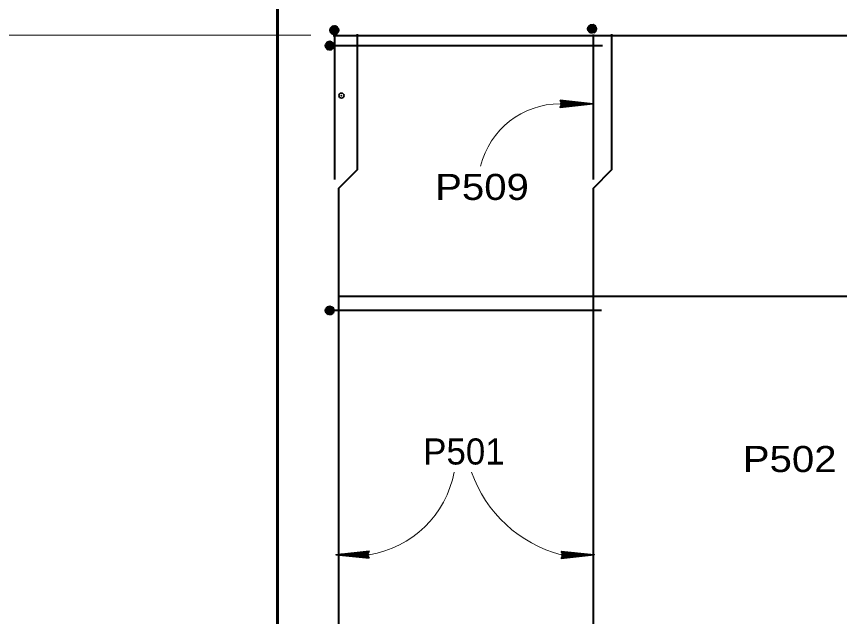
# Model space of a CAD drawing. Extents: x 4.49 to 7.69, y 0.28 to 2.27.
# Drawn here: x 4.7957 to 5.0586, y 0.8124 to 1.004 of the extents above; entities that cross this region are included whole.
import ezdxf

# ---------------------------------------------------------------- set-up
doc = ezdxf.new("R2010")
doc.units = 0
doc.header["$LTSCALE"] = 0.0033
doc.header["$PDMODE"] = 32
doc.header["$PDSIZE"] = 0.00165
doc.layers.add('1', color=7, linetype='Continuous', lineweight=35)

msp = doc.modelspace()

# ---------------------------------------------------------------- linework, layer by layer
at = {"layer": '1', "lineweight": 40}
for p, q in [((4.89625, 0.998833), (4.896583, 1.00075)), ((4.896417, 0.99875), (4.89675, 1.00075)), ((4.896417, 0.99975), (4.897917, 0.999667)), ((4.896417, 0.999667), (4.897917, 0.999583)), ((4.896417, 0.999583), (4.897917, 0.9995)), ((4.896417, 0.9995), (4.897917, 0.999417)), ((4.896417, 0.999417), (4.897917, 0.999333)), ((4.896417, 0.999333), (4.897917, 0.99925)), ((4.896417, 0.99925), (4.897917, 0.999167)), ((4.896417, 0.999083), (4.897917, 0.999)), ((4.896417, 0.999), (4.897917, 0.998917)), ((4.896417, 0.998917), (4.897917, 0.998833)), ((4.8965, 1.000833), (4.898, 1.00075)), ((4.8965, 0.99875), (4.896833, 1.00075)), ((4.8965, 1.000667), (4.898, 1.000583)), ((4.8965, 1.000583), (4.898, 1.0005)), ((4.8965, 1.0005), (4.898, 1.000417)), ((4.8965, 1.000417), (4.898, 1.000333)), ((4.8965, 1.000333), (4.898, 1.00025)), ((4.8965, 1.00025), (4.898, 1.000167)), ((4.8965, 1.000167), (4.898, 1.000083)), ((4.8965, 1.000167), (4.898, 1.000083)), ((4.8965, 1.000083), (4.898, 0.999917)), ((4.8965, 0.999917), (4.898, 0.99975)), ((4.896583, 0.99875), (4.897, 1.00075)), ((4.896667, 0.99875), (4.897083, 1.00075)), ((4.896833, 0.99875), (4.897167, 1.000667)), ((4.896917, 0.998667), (4.89725, 1.000667)), ((4.897, 0.998667), (4.897417, 1.000667)), ((4.897083, 0.998667), (4.8975, 1.000583)), ((4.897167, 0.998667), (4.897583, 1.000583)), ((4.897333, 0.998583), (4.89775, 1.000583)), ((4.897583, 0.998583), (4.897917, 1.000583)), ((4.897667, 0.998583), (4.898, 1.0005)), ((4.89775, 0.998583), (4.898083, 1.0005)), ((4.897833, 0.9985), (4.898167, 1.0005)), ((4.978583, 0.99925), (4.978917, 1.001167)), ((4.97875, 0.999167), (4.979083, 1.001167)), ((4.97875, 1.000167), (4.98025, 1.000083)), ((4.97875, 1.000083), (4.98025, 1)), ((4.97875, 1), (4.98025, 0.999917)), ((4.97875, 0.999917), (4.98025, 0.999833)), ((4.97875, 0.999833), (4.98025, 0.99975)), ((4.97875, 0.99975), (4.98025, 0.999667)), ((4.97875, 0.999667), (4.98025, 0.999583)), ((4.97875, 0.9995), (4.98025, 0.999417)), ((4.97875, 0.999417), (4.98025, 0.999333)), ((4.97875, 0.999333), (4.98025, 0.99925)), ((4.97875, 0.99925), (4.98025, 0.999167)), ((4.97875, 0.999167), (4.98025, 0.999083)), ((4.978833, 1.00125), (4.980333, 1.001167)), ((4.978833, 0.999167), (4.979167, 1.001167)), ((4.978833, 1.001083), (4.980333, 1.001)), ((4.978833, 1.001), (4.980333, 1.000917)), ((4.978833, 1.000917), (4.980333, 1.000833)), ((4.978833, 1.000833), (4.980333, 1.00075)), ((4.978833, 1.00075), (4.980333, 1.000667)), ((4.978833, 1.000667), (4.980333, 1.000583)), ((4.978833, 1.000583), (4.980333, 1.0005)), ((4.978833, 1.000583), (4.980333, 1.0005)), ((4.978833, 1.0005), (4.980333, 1.000333)), ((4.978833, 1.000333), (4.980333, 1.000167)), ((4.978917, 0.999167), (4.979333, 1.001167)), ((4.979, 0.999167), (4.979417, 1.001167)), ((4.979167, 0.999167), (4.9795, 1.001083)), ((4.97925, 0.999083), (4.979583, 1.001083)), ((4.979333, 0.999083), (4.97975, 1.001083)), ((4.979417, 0.999083), (4.979833, 1.001)), ((4.9795, 0.999083), (4.979917, 1.001)), ((4.979667, 0.999), (4.980083, 1.001)), ((4.979917, 0.999), (4.98025, 1.001)), ((4.98, 0.999), (4.980333, 1.000917)), ((4.980083, 0.999), (4.980417, 1.000917)), ((4.980167, 0.998917), (4.9805, 1.000917)), ((4.896417, 0.998833), (4.897917, 0.99875)), ((4.896417, 0.99875), (4.897917, 0.998667)), ((4.89725, 0.99825), (4.89725, 0.951917)), ((4.979833, 0.99825), (4.979833, 0.951917)), ((4.894583, 0.994), (4.894667, 0.9955)), ((4.896667, 0.994167), (4.894667, 0.994583)), ((4.896667, 0.994083), (4.894667, 0.9945)), ((4.896667, 0.994), (4.894667, 0.994333)), ((4.896667, 0.993917), (4.894667, 0.99425)), ((4.896583, 0.99375), (4.894667, 0.994083)), ((4.89475, 0.994), (4.894833, 0.9955)), ((4.89675, 0.9945), (4.89475, 0.994917)), ((4.89675, 0.994417), (4.89475, 0.99475)), ((4.896667, 0.994333), (4.89475, 0.994667)), ((4.894833, 0.994), (4.894917, 0.9955)), ((4.896833, 0.995083), (4.894833, 0.995417)), ((4.896833, 0.994833), (4.894833, 0.99525)), ((4.89675, 0.994667), (4.894833, 0.995083)), ((4.89675, 0.994583), (4.894833, 0.995)), ((4.896917, 0.995333), (4.894917, 0.995667)), ((4.896833, 0.99525), (4.894917, 0.995583)), ((4.894917, 0.994), (4.895, 0.9955)), ((4.896833, 0.995167), (4.894917, 0.9955)), ((4.895, 0.994), (4.895083, 0.9955)), ((4.895083, 0.994), (4.895167, 0.9955)), ((4.895167, 0.994), (4.89525, 0.9955)), ((4.89525, 0.994), (4.895333, 0.9955)), ((4.89525, 0.994), (4.895333, 0.9955)), ((4.895333, 0.994), (4.8955, 0.9955)), ((4.8955, 0.994), (4.895667, 0.9955)), ((4.895667, 0.993917), (4.89575, 0.995417)), ((4.89575, 0.993917), (4.895833, 0.995417)), ((4.895833, 0.993917), (4.895917, 0.995417)), ((4.895917, 0.993917), (4.896, 0.995417)), ((4.896, 0.993917), (4.896083, 0.995417)), ((4.896083, 0.993917), (4.896167, 0.995417)), ((4.896167, 0.993917), (4.89625, 0.995417)), ((4.896333, 0.993917), (4.896417, 0.995417)), ((4.896417, 0.993917), (4.8965, 0.995417)), ((4.8965, 0.993917), (4.896583, 0.995417)), ((4.896583, 0.993917), (4.896667, 0.995417)), ((4.896667, 0.993917), (4.89675, 0.995417)), ((4.897167, 0.99475), (4.982833, 0.99475)), ((4.8985, 0.914667), (5.122167, 0.914667)), ((4.894583, 0.909417), (4.894667, 0.910917)), ((4.896667, 0.909583), (4.894667, 0.91)), ((4.896667, 0.9095), (4.894667, 0.909917)), ((4.896667, 0.909417), (4.894667, 0.90975)), ((4.896667, 0.909333), (4.894667, 0.909667)), ((4.896583, 0.909167), (4.894667, 0.9095)), ((4.89475, 0.909417), (4.894833, 0.910917)), ((4.89675, 0.909917), (4.89475, 0.910333)), ((4.89675, 0.909833), (4.89475, 0.910167)), ((4.896667, 0.90975), (4.89475, 0.910083)), ((4.894833, 0.909417), (4.894917, 0.910917)), ((4.896833, 0.9105), (4.894833, 0.910833)), ((4.896833, 0.91025), (4.894833, 0.910667)), ((4.89675, 0.910083), (4.894833, 0.9105)), ((4.89675, 0.91), (4.894833, 0.910417)), ((4.896917, 0.91075), (4.894917, 0.911083)), ((4.896833, 0.910667), (4.894917, 0.911)), ((4.894917, 0.909417), (4.895, 0.910917)), ((4.896833, 0.910583), (4.894917, 0.910917)), ((4.895, 0.909417), (4.895083, 0.910917)), ((4.895083, 0.909417), (4.895167, 0.910917)), ((4.895167, 0.909417), (4.89525, 0.910917)), ((4.89525, 0.909417), (4.895333, 0.910917)), ((4.89525, 0.909417), (4.895333, 0.910917)), ((4.895333, 0.909417), (4.8955, 0.910917)), ((4.8955, 0.909417), (4.895667, 0.910917)), ((4.895667, 0.909333), (4.89575, 0.910833)), ((4.89575, 0.909333), (4.895833, 0.910833)), ((4.895833, 0.909333), (4.895917, 0.910833)), ((4.895917, 0.909333), (4.896, 0.910833)), ((4.896, 0.909333), (4.896083, 0.910833)), ((4.896083, 0.909333), (4.896167, 0.910833)), ((4.896167, 0.909333), (4.89625, 0.910833)), ((4.896333, 0.909333), (4.896417, 0.910833)), ((4.896417, 0.909333), (4.8965, 0.910833)), ((4.8965, 0.909333), (4.896583, 0.910833)), ((4.896583, 0.909333), (4.896667, 0.910833)), ((4.896667, 0.909333), (4.89675, 0.910833)), ((4.897167, 0.910167), (4.9825, 0.910167))]:
    msp.add_line(p, q, dxfattribs=at)
at = {"layer": '1', "lineweight": 13}
msp.add_line((4.88975, 0.998083), (4.7125, 0.998083), dxfattribs=at)
at = {"layer": '1'}
for p, q in [((4.969333, 0.976167), (4.979917, 0.976167)), ((4.9695, 0.9755), (4.976833, 0.97625)), ((4.969583, 0.977167), (4.977417, 0.97625)), ((4.969583, 0.977167), (4.977417, 0.97625)), ((4.969583, 0.977083), (4.977417, 0.97625)), ((4.969583, 0.977), (4.977417, 0.976167)), ((4.969583, 0.977), (4.977417, 0.976)), ((4.969583, 0.975333), (4.976917, 0.976167)), ((4.969583, 0.97525), (4.976917, 0.976)), ((4.969583, 0.975083), (4.976917, 0.975917)), ((4.908333, 0.832083), (4.89775, 0.832083)), ((4.908083, 0.83125), (4.90025, 0.83225)), ((4.908083, 0.83125), (4.90025, 0.832083)), ((4.908083, 0.831083), (4.90025, 0.832)), ((4.908083, 0.831083), (4.90025, 0.832)), ((4.908083, 0.831167), (4.90025, 0.832)), ((4.908083, 0.833167), (4.90075, 0.832333)), ((4.908083, 0.833), (4.90075, 0.83225)), ((4.908083, 0.832917), (4.90075, 0.832083)), ((4.908167, 0.83275), (4.900833, 0.832)), ((4.969667, 0.832083), (4.98025, 0.832083)), ((4.969833, 0.831417), (4.977167, 0.832167)), ((4.969917, 0.833083), (4.97775, 0.832167)), ((4.969917, 0.833083), (4.97775, 0.832167)), ((4.969917, 0.833), (4.97775, 0.832167)), ((4.969917, 0.832917), (4.97775, 0.832083)), ((4.969917, 0.832917), (4.97775, 0.831917)), ((4.969917, 0.83125), (4.97725, 0.832083)), ((4.969917, 0.831167), (4.97725, 0.831917)), ((4.969917, 0.831), (4.97725, 0.831833))]:
    msp.add_line(p, q, dxfattribs=at)
at = {"layer": '1', "lineweight": 60}
msp.add_lwpolyline([(4.79575, 0.599083), (4.79575, 0.682417), (4.879083, 0.682417), (4.879083, 1.01575)], dxfattribs=at)
at = {"layer": '1', "lineweight": 40}
for points in [[(4.89725, 0.998333), (4.896917, 1.000917), (4.896417, 0.998583), (4.8975, 1.000917), (4.897917, 0.9985), (4.89825, 1.0005), (4.896167, 1.0005), (4.8985, 0.999583), (4.895917, 0.999833), (4.89825, 0.998833), (4.895917, 0.999167), (4.8985, 1), (4.89675, 0.998417), (4.896583, 1.000833), (4.898417, 0.999167), (4.896, 1.00025), (4.896417, 0.998583), (4.897917, 0.9985), (4.8985, 0.999583), (4.89825, 1.0005), (4.8975, 1.000917), (4.896583, 1.000833), (4.896, 1.00025), (4.897083, 0.999583), (4.898, 1.00075), (4.89825, 0.998833), (4.897083, 0.999583), (4.896583, 0.9985), (4.895917, 0.9995), (4.897, 0.999583), (4.89825, 1.000417), (4.897, 0.998417), (4.896667, 0.99975), (4.896167, 1.0005)], [(4.979583, 0.99875), (4.97925, 1.001333), (4.97875, 0.999), (4.979833, 1.001333), (4.98025, 0.998917), (4.980583, 1.000917), (4.9785, 1.000917), (4.980833, 1), (4.97825, 1.00025), (4.980583, 0.99925), (4.97825, 0.999583), (4.980833, 1.000417), (4.979083, 0.998833), (4.978917, 1.00125), (4.98075, 0.999583), (4.978333, 1.000667), (4.97875, 0.999), (4.98025, 0.998917), (4.980833, 1), (4.980583, 1.000917), (4.979833, 1.001333), (4.978917, 1.00125), (4.978333, 1.000667), (4.979417, 1), (4.980333, 1.001167), (4.980583, 0.99925), (4.979417, 1), (4.978917, 0.998917), (4.97825, 0.999917), (4.979333, 1), (4.980583, 1.000833), (4.979333, 0.998833), (4.979, 1.000167), (4.9785, 1.000917)], [(4.896833, 0.998), (5.122333, 0.998), (5.4505, 0.998)], [(4.9045, 0.998333), (4.9045, 0.955), (4.898583, 0.949083), (4.898583, 0.74075), (4.9045, 0.734833), (4.9045, 0.688583)], [(4.98575, 0.998333), (4.98575, 0.955), (4.979833, 0.949083), (4.979833, 0.74075), (4.98575, 0.734833), (4.98575, 0.688583)], [(4.897083, 0.99475), (4.8945, 0.994417), (4.896833, 0.993917), (4.8945, 0.995), (4.896917, 0.995417), (4.894917, 0.99575), (4.894917, 0.993667), (4.895833, 0.996), (4.895583, 0.993417), (4.896583, 0.99575), (4.89625, 0.993417), (4.895417, 0.996), (4.897, 0.99425), (4.894583, 0.994083), (4.89625, 0.995917), (4.895167, 0.9935), (4.896833, 0.993917), (4.896917, 0.995417), (4.895833, 0.996), (4.894917, 0.99575), (4.8945, 0.995), (4.894583, 0.994083), (4.895167, 0.9935), (4.895833, 0.994583), (4.894667, 0.9955), (4.896583, 0.99575), (4.895833, 0.994583), (4.896917, 0.994083), (4.895917, 0.993417), (4.895833, 0.9945), (4.895, 0.99575), (4.897, 0.9945), (4.895667, 0.994167), (4.894917, 0.993667)], [(4.897083, 0.910167), (4.8945, 0.909833), (4.896833, 0.909333), (4.8945, 0.910417), (4.896917, 0.910833), (4.894917, 0.911167), (4.894917, 0.909083), (4.895833, 0.911417), (4.895583, 0.908833), (4.896583, 0.911167), (4.89625, 0.908833), (4.895417, 0.911417), (4.897, 0.909667), (4.894583, 0.9095), (4.89625, 0.911333), (4.895167, 0.908917), (4.896833, 0.909333), (4.896917, 0.910833), (4.895833, 0.911417), (4.894917, 0.911167), (4.8945, 0.910417), (4.894583, 0.9095), (4.895167, 0.908917), (4.895833, 0.91), (4.894667, 0.910917), (4.896583, 0.911167), (4.895833, 0.91), (4.896917, 0.9095), (4.895917, 0.908833), (4.895833, 0.909917), (4.895, 0.911167), (4.897, 0.909917), (4.895667, 0.909583), (4.894917, 0.909083)]]:
    msp.add_lwpolyline(points, dxfattribs=at)
at = {"layer": '1'}
for points in [[(4.969333, 0.97725), (4.979917, 0.976167), (4.969333, 0.975), (4.969917, 0.976167)], [(4.970083, 0.97625), (4.97475, 0.976333), (4.97475, 0.97625), (4.973833, 0.97625), (4.970083, 0.976333), (4.973083, 0.976417), (4.969917, 0.9765), (4.972167, 0.976583), (4.969917, 0.976667), (4.973417, 0.976417), (4.978083, 0.97625), (4.977167, 0.976), (4.978417, 0.976), (4.970083, 0.976), (4.9725, 0.975833), (4.969917, 0.975833), (4.97525, 0.97625), (4.969917, 0.975583)], [(4.908333, 0.831), (4.89775, 0.832083), (4.908333, 0.83325), (4.90775, 0.832083)], [(4.907583, 0.832), (4.902917, 0.831917), (4.902917, 0.832), (4.903833, 0.832), (4.907583, 0.831917), (4.904583, 0.831833), (4.90775, 0.83175), (4.9055, 0.831667), (4.90775, 0.831583), (4.90425, 0.831833), (4.899583, 0.832), (4.9005, 0.83225), (4.89925, 0.83225), (4.907583, 0.83225), (4.905167, 0.832417), (4.90775, 0.832417), (4.902417, 0.832), (4.90775, 0.832667)], [(4.969667, 0.833167), (4.98025, 0.832083), (4.969667, 0.830917), (4.97025, 0.832083)], [(4.970417, 0.832167), (4.975083, 0.83225), (4.975083, 0.832167), (4.974167, 0.832167), (4.970417, 0.83225), (4.973417, 0.832333), (4.97025, 0.832417), (4.9725, 0.8325), (4.97025, 0.832583), (4.97375, 0.832333), (4.978417, 0.832167), (4.9775, 0.831917), (4.97875, 0.831917), (4.970417, 0.831917), (4.972833, 0.83175), (4.97025, 0.83175), (4.975583, 0.832167), (4.97025, 0.8315)]]:
    msp.add_lwpolyline(points, close=True, dxfattribs=at)
for points in [[(4.970083, 0.97625), (4.969667, 0.977), (4.969917, 0.97675), (4.970083, 0.976417), (4.970333, 0.9765), (4.970167, 0.976833), (4.97, 0.976083), (4.969833, 0.975583), (4.969583, 0.975167)], [(4.907583, 0.832), (4.908, 0.83125), (4.90775, 0.8315), (4.907583, 0.831833), (4.907333, 0.83175), (4.9075, 0.831417), (4.907667, 0.832167), (4.907833, 0.832667), (4.908083, 0.833083)], [(4.970417, 0.832167), (4.97, 0.832917), (4.97025, 0.832667), (4.970417, 0.832333), (4.970667, 0.832417), (4.9705, 0.83275), (4.970333, 0.832), (4.970167, 0.8315), (4.969917, 0.831083)]]:
    msp.add_lwpolyline(points, dxfattribs=at)
at = {"layer": '1', "lineweight": 40}
for centre in [(4.8972, 0.999667), (4.979533, 1.000083), (4.89575, 0.9947), (4.89575, 0.910117)]:
    msp.add_circle(centre, 0.00132, dxfattribs=at)
at = {"layer": '1', "lineweight": 13}
for centre, radius, start, end in [((4.969429, 0.949868), 0.026298, 90.20866, 165.95631), ((4.903111, 0.864631), 0.032964, 279.1157, 349.28048), ((4.980264, 0.872346), 0.041634, 199.42455, 255.25359)]:
    msp.add_arc(centre, radius, start, end, dxfattribs=at)
at = {"layer": '1'}
msp.add_point((4.8995, 0.97875), dxfattribs=at)

# ---------------------------------------------------------------- texts
at = {"layer": '1', "width": 1.15}
for s, p in [('P509', (4.929417, 0.945417)), ('P502', (5.027667, 0.8585))]:
    msp.add_text(s, height=0.008334, dxfattribs=at).set_placement(p)
at = {"layer": '1'}
msp.add_text('P501', height=0.008334, dxfattribs=at).set_placement((4.925583, 0.860917))

doc.saveas('drawing.dxf')
